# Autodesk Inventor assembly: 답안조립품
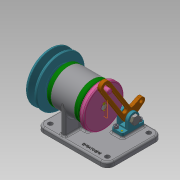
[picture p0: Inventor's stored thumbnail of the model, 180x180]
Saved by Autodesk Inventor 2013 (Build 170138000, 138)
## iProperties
Created: 2019-09
Part Number: 답안조립품
Document SubType Name: Assembly
Designer: Administrator
Mass: 1417.86 g
Surface Area: 1426.65 cm^2
Volume: 427.118 cm^3
Density: 3.31959 g/cm^3
Author: Administrator
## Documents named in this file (19)
- C:\Users\Administrator\Desktop\390904V1009\답안조립품.iam
- C:\Users\Administrator\Desktop\390904V1009\본체.ipt
- C:\Users\Administrator\Desktop\390904V1009\V-벨트풀리.ipt
- C:\Users\Administrator\Desktop\390904V1009\너트 M8.ipt
- C:\Users\Administrator\Desktop\390904V1009\너트 M10x1.ipt
- C:\Users\Administrator\Desktop\390904V1009\돌림판.ipt
- C:\Users\Administrator\Desktop\390904V1009\멈춤나사 M3x5.ipt
- C:\Users\Administrator\Desktop\390904V1009\베어링 6004.ipt
- C:\Users\Administrator\Desktop\390904V1009\볼트 M4.ipt
- C:\Users\Administrator\Desktop\390904V1009\오일 실 17 30 5.ipt
- C:\Users\Administrator\Desktop\390904V1009\와셔 8x15.5.ipt
- C:\Users\Administrator\Desktop\390904V1009\축.ipt
- C:\Users\Administrator\Desktop\390904V1009\커버.ipt
- C:\Users\Administrator\Desktop\390904V1009\크랭크.ipt
- C:\Users\Administrator\Desktop\390904V1009\키 4 x 4 x 8.ipt
- C:\Users\Administrator\Desktop\390904V1009\키 5 x 5 x 12.ipt
- C:\Users\Administrator\Desktop\390904V1009\핀 3 x 8.ipt
- C:\Users\Administrator\Desktop\390904V1009\힌지 축.ipt
- C:\Users\Administrator\Desktop\390904V1009\힌지.ipt
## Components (3 placed, 2 different names)
1. V-벨트풀리:1
2. 핀 3 x 8:1 — 플러쉬:4
3. 핀 3 x 8:2 — 플러쉬:3
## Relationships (2: Flush 2)
- 플러쉬:3 [Flush]: 핀 3 x 8:2
- 플러쉬:4 [Flush]: 핀 3 x 8:1
